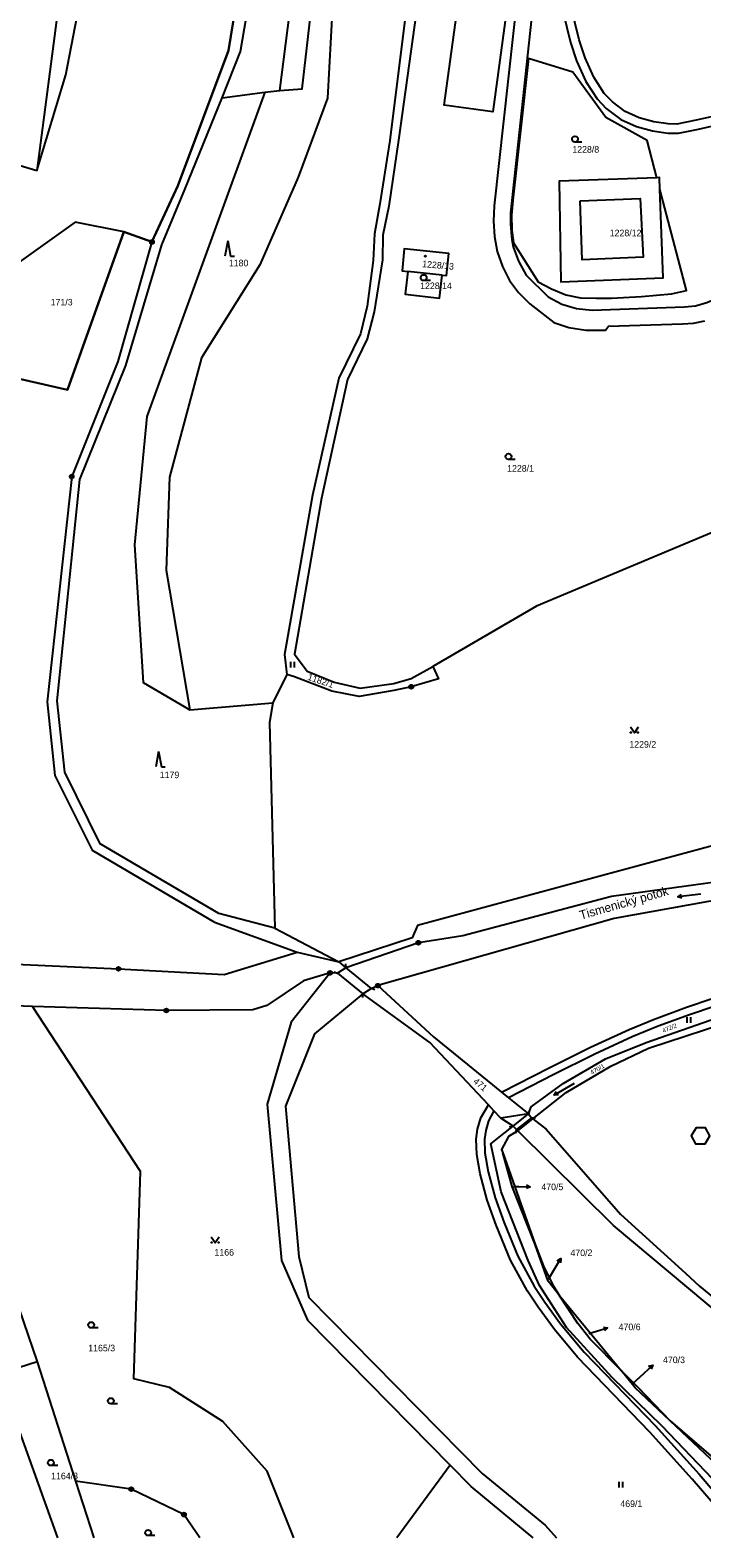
# Model space of a CAD drawing. Extents: x -737240 to -735272, y -1119606 to -1117878.
# Drawn here: x -736538.4 to -736364.4, y -1119605.2 to -1119214.7 of the extents above; entities that cross this region are included whole.
import ezdxf

# ---------------------------------------------------------------- set-up
doc = ezdxf.new("R2010")
doc.units = 0
for name, color, linetype in [('Level 1', 7, 'Continuous'), ('Level 13', 7, 'Continuous'), ('Level 15', 7, 'Continuous'), ('Level 16', 7, 'Continuous'), ('Level 18', 7, 'Continuous'), ('Level 19', 7, 'Continuous'), ('Level 25', 7, 'Continuous'), ('Level 4', 7, 'Continuous')]:
    doc.layers.add(name, color=color, linetype=linetype)

msp = doc.modelspace()

# ---------------------------------------------------------------- linework, layer by layer
at = {"layer": 'Level 1'}
for p, q in [((-736488.71, -1119232.18), (-736477.6, -1119230.7)), ((-736477.6, -1119230.7), (-736473.73, -1119230.26)), ((-736536.7, -1119251.07), (-736546.3, -1119248.23)), ((-736431.67, -1119278.11), (-736440.59, -1119277.16)), ((-736471.94, -1119381.62), (-736475.53, -1119388.96)), ((-736497.03, -1119390.77), (-736475.53, -1119388.96)), ((-736475.01, -1119447.32), (-736458.48, -1119456.01)), ((-736469.24, -1119453.5), (-736458.48, -1119456.01)), ((-736458.48, -1119456.01), (-736456.65, -1119457.58)), ((-736458.77, -1119458.92), (-736460.73, -1119458.88)), ((-736456.65, -1119457.58), (-736458.77, -1119458.92)), ((-736452.22, -1119464.28), (-736450.11, -1119462.94)), ((-736450.11, -1119462.94), (-736448.35, -1119462.19)), ((-736537.87, -1119467.58), (-736568.59, -1119466.46)), ((-736568.59, -1119466.46), (-736536.63, -1119559.66)), ((-736416.3, -1119489.76), (-736414.49, -1119491.22)), ((-736414.49, -1119491.22), (-736409.31, -1119495.41)), ((-736418.26, -1119494.6), (-736419.72, -1119493.05)), ((-736416.47, -1119496.51), (-736418.26, -1119494.6)), ((-736409.31, -1119495.41), (-736416.47, -1119496.51)), ((-736413.29, -1119498.59), (-736416.47, -1119496.51)), ((-736412.08, -1119499.84), (-736408.15, -1119496.71)), ((-736415.99, -1119505.49), (-736407.63, -1119529.23)), ((-736401.34, -1119542.35), (-736385.33, -1119561.86)), ((-736536.63, -1119559.66), (-736546.6, -1119562.83)), ((-736536.63, -1119559.66), (-736526.68, -1119590.57)), ((-736546.6, -1119562.83), (-736531.355, -1119605.245)), ((-736526.68, -1119590.57), (-736521.956, -1119605.245))]:
    msp.add_line(p, q, dxfattribs=at)
for points in [[(-736506.87, -1119269.54), (-736500.16, -1119254.99), (-736487.04, -1119219.97), (-736480.32, -1119178.48), (-736480.02, -1119155.93), (-736487.2, -1119130.36), (-736493.27, -1119111.67), (-736506.34, -1119081.97), (-736533.37, -1119053.9), (-736550.43, -1119022.72), (-736558.58, -1118990.45), (-736561.05, -1118980.66), (-736558.77, -1118964.86), (-736558.81, -1118964.03), (-736556.82, -1118955.3), (-736536.82, -1118929.89), (-736530.49, -1118917.42), (-736523.97, -1118905.01), (-736523.9, -1118904.49), (-736523.54, -1118904.51), (-736513.57, -1118880.15), (-736506.92, -1118860.92)], [(-736473.73, -1119230.26), (-736468.64, -1119190.29), (-736469.9, -1119151.7), (-736473.64, -1119134.16), (-736476.05, -1119134.89), (-736479.89, -1119127.52), (-736491.48, -1119092.7), (-736506.37, -1119063.55)], [(-736488.71, -1119232.18), (-736483.9, -1119220.23), (-736477.02, -1119179.8), (-736478.63, -1119151.26), (-736488.91, -1119113.5), (-736502.81, -1119083.13), (-736514.51, -1119069.63), (-736517.81, -1119066.41)], [(-736493.27, -1119111.67), (-736487.2, -1119130.36), (-736480.02, -1119155.93), (-736480.32, -1119178.48), (-736487.04, -1119219.97), (-736500.16, -1119254.99), (-736506.87, -1119269.54), (-736514.13, -1119266.89)], [(-736434.62, -1119116.88), (-736432.54, -1119130.71), (-736431.99, -1119138), (-736432.21, -1119149.65), (-736433.51, -1119159.15), (-736437.49, -1119180.94), (-736445.22, -1119243.27), (-736447.82, -1119259.66), (-736449.18, -1119267.43), (-736449.6, -1119274.34), (-736451.12, -1119286.19), (-736452.88, -1119293.33), (-736458.43, -1119304.86), (-736465.29, -1119335.09), (-736472.58, -1119376.4), (-736471.94, -1119381.62)], [(-736536.7, -1119251.07), (-736529.2, -1119226.2), (-736518, -1119168), (-736513.9, -1119144.6)], [(-736432, -1119164.2), (-736434.36, -1119180.98), (-736443.04, -1119243.12), (-736445.49, -1119260.28), (-736447.03, -1119267.76), (-736447.14, -1119274.13), (-736449.28, -1119287.62), (-736451.12, -1119294.64), (-736456.21, -1119305.15), (-736462.93, -1119335.92), (-736469.97, -1119376.28), (-736466.63, -1119380.74), (-736459.63, -1119383.53), (-736452.91, -1119385.11), (-736444.17, -1119383.92), (-736439.68, -1119382.59), (-736434.09, -1119379.55)], [(-736358.37, -1119219.5), (-736357.31, -1119236.05), (-736365.86, -1119238), (-736370.84, -1119239.02), (-736373.1, -1119238.97), (-736376.8, -1119238.39), (-736380.64, -1119237.35), (-736384.25, -1119235.72), (-736387.56, -1119233.23), (-736389.67, -1119231.05), (-736392.43, -1119226.85), (-736394.65, -1119221.82), (-736396.17, -1119217.14), (-736405.14, -1119180.46)], [(-736473.73, -1119230.26), (-736467.93, -1119229.85), (-736465.21, -1119205.65), (-736461.16, -1119190.47), (-736460.09, -1119208.45), (-736461.42, -1119232.25), (-736468.96, -1119252.71), (-736478.95, -1119275.45), (-736494.03, -1119299.58), (-736502.33, -1119330.49), (-736503.2, -1119354.52), (-736497.03, -1119390.77)], [(-736406.02, -1119188.26), (-736413.99, -1119262), (-736414, -1119265), (-736413.66, -1119268.91), (-736413.29, -1119270.8), (-736411.87, -1119274.54), (-736409.93, -1119278.12), (-736404.25, -1119283.76), (-736400.66, -1119285.68), (-736396.86, -1119286.78), (-736392.86, -1119287.18), (-736368.91, -1119286.32), (-736366.01, -1119286.05), (-736363.13, -1119285.22), (-736359.5, -1119283.68), (-736356.12, -1119281.69), (-736352.94, -1119279.25), (-736350.32, -1119276.22), (-736348.2, -1119272.9), (-736346.64, -1119269.31), (-736338, -1119241.65), (-736336.72, -1119236.91), (-736336.1, -1119233.59)], [(-736406.02, -1119188.26), (-736405.36, -1119189.52), (-736398.47, -1119217.84), (-736396.91, -1119222.59), (-736394.49, -1119227.98), (-736391.55, -1119232.46), (-736389.22, -1119234.96), (-736385.41, -1119237.79), (-736381.33, -1119239.64), (-736377.22, -1119240.73), (-736373.18, -1119241.36), (-736370.46, -1119241.35), (-736365.31, -1119240.32), (-736336.1, -1119233.59)], [(-736560.76, -1119194.73), (-736542.26, -1119198.35), (-736543.14, -1119205.59), (-736530.95, -1119206.78), (-736536.7, -1119251.07)], [(-736416.46, -1119193.17), (-736412.86, -1119193.65), (-736418.52, -1119235.83), (-736431.2, -1119234.09), (-736425.37, -1119191.97), (-736420.28, -1119192.65)], [(-736416.46, -1119193.17), (-736416.07, -1119192.02), (-736414.62, -1119191.07), (-736412.69, -1119191.29), (-736411.29, -1119192.64), (-736410.91, -1119193.53), (-736418.18, -1119260.14), (-736418.39, -1119264.12), (-736418.11, -1119268.16), (-736417.47, -1119272.03), (-736416.04, -1119275.88), (-736414.27, -1119279.52), (-736411.94, -1119282.61), (-736408.98, -1119285.54), (-736402.76, -1119290.39), (-736398.89, -1119291.66), (-736394.47, -1119292.35), (-736389.35, -1119292.41), (-736388.62, -1119291.37), (-736369.44, -1119290.73), (-736366.57, -1119290.55), (-736363.63, -1119289.96)], [(-736376.06, -1119252.89), (-736378.6, -1119243.23), (-736389.32, -1119237.33), (-736397.86, -1119225.58), (-736409.32, -1119222.04), (-736413.36, -1119258.69), (-736413.73, -1119262.6), (-736413.61, -1119266.44), (-736413.23, -1119269.78), (-736406.8, -1119279.87), (-736403.34, -1119281.71), (-736399.65, -1119283.26), (-736395.82, -1119283.98), (-736391.8, -1119284.09), (-736387.83, -1119284.06), (-736380, -1119283.67), (-736372.25, -1119282.95), (-736368.38, -1119282.1), (-736375.28, -1119255.86)], [(-736475.01, -1119447.32), (-736489.59, -1119443.46), (-736520.27, -1119425.42), (-736529.45, -1119406.93), (-736531.46, -1119388.4), (-736525.61, -1119331.11), (-736513.61, -1119301.51), (-736504.35, -1119270.28), (-736498.39, -1119255.97), (-736488.71, -1119232.18)], [(-736477.6, -1119230.7), (-736508.19, -1119314.78), (-736511.38, -1119348.01), (-736509.18, -1119383.65), (-736497.03, -1119390.77)], [(-736376.06, -1119252.89), (-736401.35, -1119253.75), (-736400.92, -1119279.87), (-736374.43, -1119278.85), (-736375.28, -1119255.86)], [(-736375.28, -1119255.86), (-736375.39, -1119252.87), (-736376.06, -1119252.89)], [(-736514.13, -1119266.89), (-736526.79, -1119264.4), (-736541.31, -1119274.79)], [(-736552.7, -1119302.39), (-736528.73, -1119307.83), (-736514.13, -1119266.89), (-736506.87, -1119269.54)], [(-736514.13, -1119266.89), (-736528.73, -1119307.83), (-736552.7, -1119302.39), (-736541.31, -1119274.79)], [(-736506.87, -1119269.54), (-736515.73, -1119300.49), (-736527.66, -1119330.3), (-736534.01, -1119388.71), (-736532.05, -1119407.73), (-736522.39, -1119427.13), (-736490.69, -1119445.75), (-736469.24, -1119453.5)], [(-736431.67, -1119278.11), (-736430.55, -1119278.22), (-736429.97, -1119272.52), (-736441.49, -1119271.35), (-736442.09, -1119277), (-736440.59, -1119277.16)], [(-736440.59, -1119277.16), (-736441.28, -1119283.09), (-736432.34, -1119284.09), (-736431.67, -1119278.11)], [(-736330.86, -1119325.76), (-736340.66, -1119332.73), (-736349.44, -1119338.42), (-736358.59, -1119343.47), (-736407.27, -1119363.87), (-736434.09, -1119379.55)], [(-736434.09, -1119379.55), (-736432.61, -1119382.69), (-736439.68, -1119384.76), (-736444.17, -1119385.73), (-736453.18, -1119387.27), (-736460.29, -1119385.94), (-736469.95, -1119382.15), (-736471.94, -1119381.62)], [(-736475.53, -1119388.96), (-736476.4, -1119394), (-736475.01, -1119447.32)], [(-736326.27, -1119416.42), (-736438.09, -1119446.65), (-736439.48, -1119449.82), (-736458.48, -1119456.01)], [(-736326.88, -1119432.2), (-736336.57, -1119432.04), (-736387.8, -1119439.13), (-736426.3, -1119449.27), (-736437.85, -1119451.09), (-736456.65, -1119457.58)], [(-736295.32, -1119454.3), (-736327.55, -1119446.88), (-736343.15, -1119437.49), (-736362.67, -1119440.38), (-736387.08, -1119444.81), (-736448.35, -1119462.19)], [(-736556.6, -1119455.53), (-736542.17, -1119456.67), (-736515.54, -1119457.83), (-736488.14, -1119459.31), (-736469.24, -1119453.5)], [(-736416.3, -1119489.76), (-736403.98, -1119483.46), (-736393.26, -1119478.1), (-736383.27, -1119473.51), (-736376.96, -1119470.92), (-736368.37, -1119467.75), (-736361.73, -1119465.51), (-736355.01, -1119463.57), (-736347.47, -1119461.86), (-736340.1, -1119460.53), (-736331.11, -1119459.29), (-736308.59, -1119456.68), (-736305.59, -1119456.6), (-736300.49, -1119457.33)], [(-736460.73, -1119458.88), (-736467.6, -1119460.98), (-736477.09, -1119467.35), (-736480.7, -1119468.5), (-736503.15, -1119468.63), (-736537.87, -1119467.58)], [(-736460.73, -1119458.88), (-736470.78, -1119471.65), (-736476.99, -1119492.89), (-736473.31, -1119533.4), (-736466.61, -1119548.86), (-736429.63, -1119586.45)], [(-736305.77, -1119458.68), (-736308.44, -1119458.81), (-736331.27, -1119461.44), (-736340.19, -1119462.69), (-736347.11, -1119463.94), (-736354.48, -1119465.62), (-736360.93, -1119467.47), (-736367.59, -1119469.75), (-736375.72, -1119472.71), (-736382.44, -1119475.46), (-736392.16, -1119479.91), (-736402.9, -1119485.32), (-736414.49, -1119491.22)], [(-736409.31, -1119495.41), (-736408.61, -1119493.56), (-736400.37, -1119487.54), (-736389.34, -1119481.13), (-736378.85, -1119476.95), (-736354.78, -1119468.53), (-736340.73, -1119465.79), (-736328.8, -1119464.09), (-736316.7, -1119461.59), (-736308.94, -1119459.39), (-736305.77, -1119458.68)], [(-736408.15, -1119496.71), (-736399.55, -1119489.88), (-736388.02, -1119483.03), (-736378.26, -1119478.37), (-736353.93, -1119470.43), (-736341.03, -1119467.7), (-736328.39, -1119465.75), (-736306.43, -1119461.47), (-736305.1, -1119462.1), (-736304.49, -1119462.02), (-736299.58, -1119459.62)], [(-736452.22, -1119464.28), (-736464.76, -1119474.65), (-736472.3, -1119493.42), (-736468.84, -1119532.33), (-736466.23, -1119542.94), (-736421.32, -1119588.58), (-736404.96, -1119601.96), (-736402.057, -1119605.245)], [(-736419.72, -1119493.05), (-736434.88, -1119476.92), (-736452.22, -1119464.28)], [(-736448.35, -1119462.19), (-736433.95, -1119475.48), (-736416.3, -1119489.76)], [(-736470.134, -1119605.245), (-736477.06, -1119587.93), (-736488.55, -1119575.12), (-736502.32, -1119566.26), (-736511.57, -1119564.01), (-736509.83, -1119510.32), (-736537.87, -1119467.58)], [(-736353.846, -1119605.245), (-736355.01, -1119603.86), (-736366.89, -1119590.05), (-736377.84, -1119577.88), (-736396.58, -1119558.45), (-736402.62, -1119551.24), (-736406.79, -1119545.52), (-736409.54, -1119541.32), (-736413.98, -1119533.29), (-736417.7, -1119524.28), (-736420, -1119517.73), (-736421.86, -1119510.91), (-736422.73, -1119505.93), (-736422.85, -1119501.98), (-736422.52, -1119499.35), (-736421.67, -1119496.47), (-736419.72, -1119493.05)], [(-736418.26, -1119494.6), (-736419.7, -1119497.23), (-736420.4, -1119499.69), (-736420.73, -1119502), (-736420.65, -1119505.48), (-736419.8, -1119510.44), (-736417.94, -1119517.18), (-736415.65, -1119523.62), (-736412.12, -1119532.27), (-736407.83, -1119540.03), (-736405.12, -1119544.17), (-736400.99, -1119549.8), (-736394.92, -1119557.12), (-736376.46, -1119576.16), (-736365.12, -1119588.73), (-736353.45, -1119602.4), (-736351.046, -1119605.245)], [(-736346.704, -1119605.245), (-736352.36, -1119599.46), (-736355.29, -1119596.17), (-736361.65, -1119590), (-736374.68, -1119576.29), (-736387.64, -1119563.67), (-736399.47, -1119550.79), (-736406.5, -1119539.83), (-736409.43, -1119533.42), (-736416.41, -1119515.59), (-736419.05, -1119503.19), (-736416.04, -1119500.72), (-736413.29, -1119498.59)], [(-736408.15, -1119496.71), (-736404.78, -1119499.39), (-736385.5, -1119521.39), (-736368.62, -1119536.68), (-736365.03, -1119540.02), (-736341.83, -1119559), (-736338.15, -1119562.28), (-736327.08, -1119572.14), (-736301.93, -1119601.25), (-736298.088, -1119605.245)], [(-736412.08, -1119499.84), (-736414.52, -1119501.27), (-736416.28, -1119504.68), (-736415.99, -1119505.49)], [(-736301.675, -1119605.245), (-736344.04, -1119560.54), (-736387.29, -1119524.37), (-736412.08, -1119499.84)], [(-736407.63, -1119529.23), (-736413.56, -1119514.26), (-736415.99, -1119505.49)], [(-736401.34, -1119542.35), (-736404.26, -1119538.79), (-736407.63, -1119529.23)], [(-736407.63, -1119529.23), (-736405.41, -1119534.83), (-736402.87, -1119540.02), (-736401.34, -1119542.35)], [(-736385.33, -1119561.86), (-736393.36, -1119553.8), (-736396.52, -1119549.68), (-736401.34, -1119542.35)], [(-736385.33, -1119561.86), (-736380.9, -1119566.31), (-736372.57, -1119574.91)], [(-736372.57, -1119574.91), (-736381.64, -1119566.36), (-736385.33, -1119561.86)], [(-736342.632, -1119605.245), (-736362.05, -1119584.82), (-736372.57, -1119574.91)], [(-736372.57, -1119574.91), (-736360.18, -1119585.64), (-736351.93, -1119593), (-736349.67, -1119596.61), (-736344.16, -1119600.82), (-736340.524, -1119605.245)], [(-736429.63, -1119586.45), (-736443.399, -1119605.245)], [(-736408.088, -1119605.245), (-736424.15, -1119591.98), (-736429.63, -1119586.45)], [(-736494.477, -1119605.245), (-736498.58, -1119599.21), (-736512.24, -1119592.63), (-736526.68, -1119590.57)]]:
    msp.add_lwpolyline(points, dxfattribs=at)
at = {"layer": 'Level 13'}
msp.add_lwpolyline([(-736480.32, -1119178.48), (-736487.04, -1119219.97), (-736500.16, -1119254.99), (-736506.87, -1119269.54), (-736514.13, -1119266.89), (-736528.73, -1119307.83), (-736552.7, -1119302.39), (-736541.31, -1119274.79), (-736547.66, -1119273.19), (-736583.76, -1119264.06), (-736590.7, -1119265.63), (-736639.96, -1119239.42), (-736665.92, -1119231.67), (-736662.64, -1119204.74)], dxfattribs=at)
msp.add_lwpolyline([(-736480.32, -1119178.48), (-736487.04, -1119219.97), (-736500.16, -1119254.99), (-736506.87, -1119269.54), (-736514.13, -1119266.89), (-736528.73, -1119307.83), (-736552.7, -1119302.39), (-736541.31, -1119274.79), (-736547.66, -1119273.19), (-736583.76, -1119264.06), (-736590.7, -1119265.63), (-736639.96, -1119239.42), (-736665.92, -1119231.67), (-736662.64, -1119204.74)], dxfattribs=at)
at = {"layer": 'Level 16'}
for points in [[(-736413.24, -1119514.2), (-736411.86, -1119514.23), (-736408.861, -1119514.301)], [(-736409.849, -1119513.777), (-736408.861, -1119514.301), (-736409.872, -1119514.777)], [(-736404.14, -1119538.23), (-736402.49, -1119535.47), (-736400.953, -1119532.894)], [(-736401.894, -1119533.496), (-736400.953, -1119532.894), (-736401.036, -1119534.009)], [(-736393.71, -1119552.3), (-736391.68, -1119551.69), (-736388.809, -1119550.821)], [(-736389.911, -1119550.632), (-736388.809, -1119550.821), (-736389.621, -1119551.589)], [(-736382.24, -1119565.25), (-736379.33, -1119562.54), (-736377.136, -1119560.493)], [(-736378.209, -1119560.81), (-736377.136, -1119560.493), (-736377.527, -1119561.541)]]:
    msp.add_lwpolyline(points, dxfattribs=at)
at = {"layer": 'Level 25'}
for p, q in [((-736395.498, -1119243.65), (-736397.28, -1119243.65)), ((-736487.252, -1119269.219), (-736487.985, -1119273.219)), ((-736487.252, -1119269.219), (-736486.519, -1119273.219)), ((-736486.519, -1119273.219), (-736485.519, -1119273.219)), ((-736434.698, -1119279.54), (-736436.48, -1119279.54)), ((-736412.728, -1119325.88), (-736414.51, -1119325.88)), ((-736470.957, -1119378.315), (-736470.957, -1119379.815)), ((-736469.935, -1119379.815), (-736469.935, -1119378.315)), ((-736505.152, -1119401.539), (-736505.885, -1119405.539)), ((-736505.152, -1119401.539), (-736504.419, -1119405.539)), ((-736504.419, -1119405.539), (-736503.419, -1119405.539)), ((-736364.691, -1119438.465), (-736370.649, -1119439.175)), ((-736456.703, -1119456.583), (-736456.65, -1119457.58)), ((-736459.728, -1119458.635), (-736458.77, -1119458.92)), ((-736452.245, -1119465.289), (-736452.22, -1119464.28)), ((-736449.174, -1119463.293), (-736450.11, -1119462.94)), ((-736368.257, -1119470.365), (-736368.257, -1119471.865)), ((-736367.235, -1119471.865), (-736367.235, -1119470.365)), ((-736397.456, -1119487.513), (-736402.644, -1119490.527)), ((-736409.033, -1119494.449), (-736409.31, -1119495.41)), ((-736414.27, -1119498.786), (-736413.29, -1119498.59)), ((-736412.65, -1119500.467), (-736412.44, -1119499.49)), ((-736407.542, -1119496.493), (-736408.54, -1119496.4)), ((-736520.858, -1119550.86), (-736522.64, -1119550.86)), ((-736515.768, -1119570.54), (-736517.55, -1119570.54)), ((-736531.298, -1119586.53), (-736533.08, -1119586.53)), ((-736385.917, -1119590.715), (-736385.917, -1119592.215)), ((-736384.895, -1119592.215), (-736384.895, -1119590.715)), ((-736506.098, -1119604.67), (-736507.88, -1119604.67))]:
    msp.add_line(p, q, dxfattribs=at)
for points in [[(-736380.88, -1119395.19), (-736381.88, -1119396.69), (-736382.88, -1119395.19)], [(-736369.597, -1119439.553), (-736370.649, -1119439.175), (-736369.715, -1119438.56)], [(-736401.528, -1119490.457), (-736402.644, -1119490.527), (-736402.031, -1119489.593)], [(-736489.5, -1119527.34), (-736490.5, -1119528.84), (-736491.5, -1119527.34)]]:
    msp.add_lwpolyline(points, dxfattribs=at)
for centre in [(-736382.78, -1119396.59), (-736380.98, -1119396.59), (-736491.4, -1119528.74), (-736489.6, -1119528.74)]:
    msp.add_circle(centre, 0.1, dxfattribs=at)
for centre, major_axis, ratio in [((-736397.28, -1119242.894), (0.764, 0), 0.9894236), ((-736506.87, -1119269.54), (0.516, 0), 0.9848078), ((-736506.87, -1119269.54), (0.0375, 0), 0.9848078), ((-736436.03, -1119273.21), (0.18, 0), 0.9848078), ((-736436.48, -1119278.784), (0.764, 0), 0.9894236), ((-736414.51, -1119325.124), (0.764, 0), 0.9894236), ((-736527.66, -1119330.3), (0.516, 0), 0.9848078), ((-736527.66, -1119330.3), (0.0375, 0), 0.9848078), ((-736439.68, -1119384.76), (0.516, 0), 0.9848078), ((-736439.68, -1119384.76), (0.0375, 0), 0.9848078), ((-736437.85, -1119451.09), (0.516, 0), 0.9848078), ((-736437.85, -1119451.09), (0.0375, 0), 0.9848078), ((-736515.54, -1119457.83), (0.516, 0), 0.9848078), ((-736515.54, -1119457.83), (0.0375, 0), 0.9848078), ((-736460.73, -1119458.88), (0.516, 0), 0.9848078), ((-736460.73, -1119458.88), (0.0375, 0), 0.9848078), ((-736448.35, -1119462.19), (0.516, 0), 0.9848078), ((-736448.35, -1119462.19), (0.0375, 0), 0.9848078), ((-736503.15, -1119468.63), (0.516, 0), 0.9848078), ((-736503.15, -1119468.63), (0.0375, 0), 0.9848078), ((-736522.64, -1119550.104), (0.764, 0), 0.9894236), ((-736517.55, -1119569.784), (0.764, 0), 0.9894236), ((-736533.08, -1119585.774), (0.764, 0), 0.9894236), ((-736512.24, -1119592.63), (0.516, 0), 0.9848078), ((-736512.24, -1119592.63), (0.0375, 0), 0.9848078), ((-736498.58, -1119599.21), (0.516, 0), 0.9848078), ((-736498.58, -1119599.21), (0.0375, 0), 0.9848078), ((-736507.88, -1119603.914), (0.764, 0), 0.9894236)]:
    msp.add_ellipse(centre, major_axis=major_axis, ratio=ratio, dxfattribs=at)
at = {"layer": 'Level 4'}
for p, q in [((-736458.77, -1119458.92), (-736452.22, -1119464.28)), ((-736456.65, -1119457.58), (-736450.11, -1119462.94)), ((-736413.29, -1119498.59), (-736409.31, -1119495.41))]:
    msp.add_line(p, q, dxfattribs=at)
for points in [[(-736395.95, -1119258.88), (-736380.39, -1119258.29), (-736379.61, -1119273.44), (-736395.38, -1119274.12), (-736395.95, -1119258.88)], [(-736409.31, -1119495.41), (-736408.54, -1119496.4), (-736412.44, -1119499.49), (-736413.29, -1119498.59)], [(-736363.58, -1119503.14), (-736362.37, -1119501.14), (-736363.48, -1119499.02), (-736365.86, -1119498.99), (-736367.14, -1119501.07), (-736366.02, -1119503.16), (-736363.58, -1119503.14)]]:
    msp.add_lwpolyline(points, dxfattribs=at)

# ---------------------------------------------------------------- texts
at = {"layer": 'Level 15'}
msp.add_text('Tismenický potok', height=2.3, rotation=15.77439, dxfattribs=at).set_placement((-736395.726, -1119445.109))
at = {"layer": 'Level 16'}
for s, p in [('470/5', (-736405.985, -1119515.17)), ('470/2', (-736398.445, -1119532.25)), ('470/6', (-736385.965, -1119551.45)), ('470/3', (-736374.465, -1119559.98))]:
    msp.add_text(s, height=1.7, dxfattribs=at).set_placement(p)
at = {"layer": 'Level 18'}
for s, height, p in [('1228/8', 1.7, (-736397.96, -1119246.4)), ('1228/12', 1.7, (-736388.265, -1119268.05)), ('1180', 1.7, (-736486.96, -1119275.84)), ('1228/14', 1.7, (-736437.385, -1119281.74)), ('171/3', 1.7, (-736533.125, -1119285.98)), ('1228/1', 1.7, (-736414.85, -1119329.04)), ('1229/2', 1.7, (-736383.18, -1119400.54)), ('1179', 1.7, (-736504.86, -1119408.44)), ('470/5', 0.1, (-736413.115, -1119514.2)), ('1166', 1.7, (-736490.68, -1119532.13)), ('470/2', 0.1, (-736404.015, -1119538.23)), ('470/6', 0.1, (-736393.585, -1119552.3)), ('1165/3', 1.7, (-736523.38, -1119556.93)), ('470/3', 0.1, (-736382.115, -1119565.25)), ('1164/3', 1.7, (-736533, -1119590.07)), ('469/1', 1.7, (-736385.52, -1119597.25))]:
    msp.add_text(s, height=height, dxfattribs=at).set_placement(p)
for s, height, rotation, p in [('1182/1', 1.7, 341.61264, (-736466.71, -1119382.924)), ('472/2', 1.14, 21.80871, (-736374.4, -1119474.43)), ('470/1', 1.14, 30.16269, (-736392.88, -1119485.3)), ('471', 1.7, 319.79988, (-736423.786, -1119487.243))]:
    msp.add_text(s, height=height, rotation=rotation, dxfattribs=at).set_placement(p)
at = {"layer": 'Level 19'}
msp.add_text('1228/13', height=1.7, rotation=355.17159, dxfattribs=at).set_placement((-736436.902, -1119276.046))

doc.saveas('drawing.dxf')
